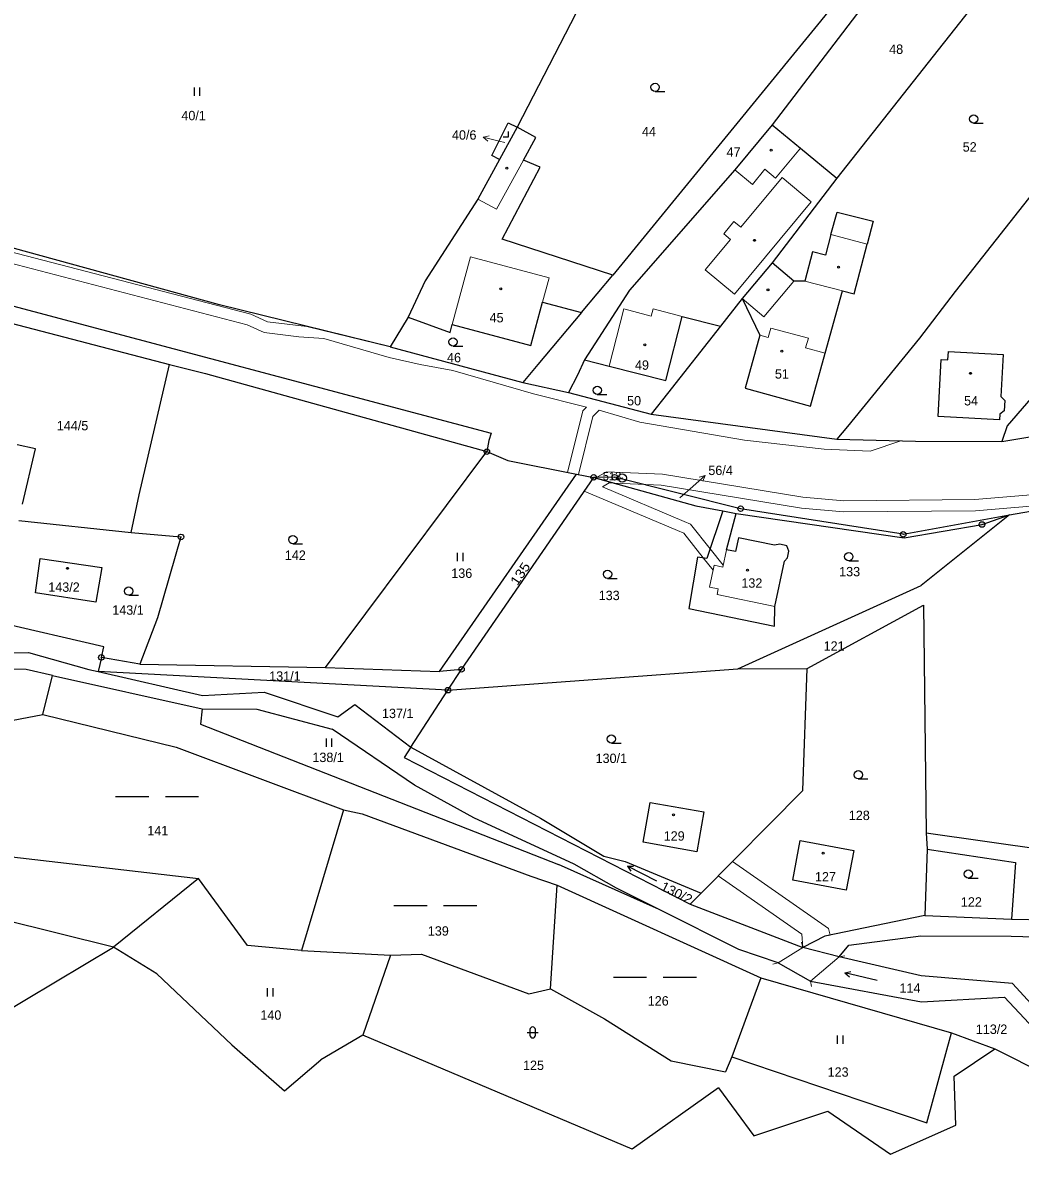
# Model space of a CAD drawing. Extents: x -727701 to -724405, y -960481 to -957284.
# Drawn here: x -726527.9 to -726347.6, y -958284.2 to -958076.9 of the extents above; entities that cross this region are included whole.
import ezdxf
from ezdxf.enums import TextEntityAlignment as Align

# ---------------------------------------------------------------- set-up
doc = ezdxf.new("R2010")
doc.units = 0
doc.header["$LTSCALE"] = 0.68
for name, color, linetype, lineweight in [('1', 7, 'Continuous', 25), ('13', 7, 'Continuous', 13), ('3', 7, 'Continuous', 25), ('4', 7, 'Continuous', 13), ('5', 7, 'Continuous', 25), ('7', 7, 'Continuous', 13), ('8', 7, 'Continuous', 25)]:
    doc.layers.add(name, color=color, linetype=linetype, lineweight=lineweight)
doc.layers.add('2', color=7, linetype='Continuous')

msp = doc.modelspace()

# ---------------------------------------------------------------- linework, layer by layer
at = {"layer": '1'}
for p, q in [((-726341.41, -958055.03), (-726380.73, -958104.97)), ((-726373.89, -958064.49), (-726421.22, -958122.51)), ((-726368.44, -958063.92), (-726392.44, -958095.31)), ((-726427.95, -958075.18), (-726438.54, -958095.75)), ((-726438.54, -958095.75), (-726441.73, -958101.6)), ((-726435.16, -958097.6), (-726438.54, -958095.75)), ((-726392.44, -958095.31), (-726399.17, -958103.47)), ((-726392.44, -958095.31), (-726387.34, -958099.52)), ((-726336.78, -958096.77), (-726359.33, -958125.49)), ((-726437.41, -958101.73), (-726435.16, -958097.6)), ((-726387.34, -958099.52), (-726380.73, -958104.97)), ((-726441.73, -958101.6), (-726445.63, -958108.76)), ((-726441.25, -958116.02), (-726434.4, -958103)), ((-726434.4, -958103), (-726437.41, -958101.73)), ((-726399.17, -958103.47), (-726418.2, -958125.25)), ((-726380.73, -958104.97), (-726392.43, -958120.31)), ((-726445.63, -958108.76), (-726455.15, -958123.51)), ((-726381.83, -958115.18), (-726380.71, -958111.11)), ((-726380.71, -958111.11), (-726374.16, -958112.74)), ((-726374.16, -958112.74), (-726375.25, -958116.9)), ((-726381.83, -958115.18), (-726382.79, -958118.88)), ((-726492.36, -958127.89), (-726536.67, -958115.73)), ((-726421.22, -958122.51), (-726441.25, -958116.02)), ((-726377.6, -958125.9), (-726375.25, -958116.9)), ((-726566.79, -958118.23), (-726443.24, -958151.08)), ((-726385.12, -958118.27), (-726386.5, -958123.57)), ((-726382.79, -958118.88), (-726385.12, -958118.27)), ((-726392.43, -958120.31), (-726397.85, -958126.74)), ((-726388.53, -958123.6), (-726392.43, -958120.31)), ((-726325.56, -958121.52), (-726349.96, -958149.77)), ((-726455.15, -958123.51), (-726458.25, -958130.09)), ((-726426.88, -958129.25), (-726421.22, -958122.51)), ((-726386.5, -958123.57), (-726388.53, -958123.6)), ((-726418.2, -958125.25), (-726426.33, -958137.83)), ((-726382.86, -958136.64), (-726379.74, -958125.34)), ((-726379.74, -958125.34), (-726377.6, -958125.9)), ((-726359.33, -958125.49), (-726365.78, -958133.91)), ((-726461.51, -958135.46), (-726492.36, -958127.89)), ((-726436.03, -958135.24), (-726433.93, -958127.37)), ((-726433.93, -958127.37), (-726426.88, -958129.25)), ((-726397.85, -958126.74), (-726401.77, -958131.72)), ((-726397.85, -958126.74), (-726394.67, -958133.38)), ((-726458.25, -958130.09), (-726461.51, -958135.46)), ((-726458.25, -958130.09), (-726450.64, -958132.86)), ((-726426.88, -958129.25), (-726434.77, -958138.64)), ((-726411.65, -958141.55), (-726408.71, -958129.96)), ((-726408.71, -958129.96), (-726401.77, -958131.72)), ((-726531.37, -958130.82), (-726501.37, -958138.64)), ((-726450.64, -958132.86), (-726450.26, -958131.44)), ((-726450.26, -958131.44), (-726436.03, -958135.24)), ((-726401.77, -958131.72), (-726411.37, -958143.91)), ((-726394.67, -958133.38), (-726397.32, -958142.97)), ((-726365.78, -958133.91), (-726378.81, -958149.88)), ((-726461.51, -958135.46), (-726437.48, -958141.93)), ((-726360.67, -958137.83), (-726360.58, -958136.33)), ((-726360.58, -958136.33), (-726350.67, -958136.87)), ((-726426.33, -958137.83), (-726427.64, -958140.61)), ((-726426.33, -958137.83), (-726421.9, -958138.95)), ((-726385.52, -958146.23), (-726382.86, -958136.64)), ((-726362.43, -958148.09), (-726361.87, -958137.77)), ((-726361.87, -958137.77), (-726360.67, -958137.83)), ((-726350.67, -958136.87), (-726351.08, -958144.46)), ((-726506.88, -958162.26), (-726501.37, -958138.64)), ((-726501.37, -958138.64), (-726494.88, -958140.3)), ((-726494.88, -958140.3), (-726444, -958154.43)), ((-726434.77, -958138.64), (-726437.48, -958141.93)), ((-726421.9, -958138.95), (-726411.65, -958141.55)), ((-726437.48, -958141.93), (-726429.23, -958143.74)), ((-726427.64, -958140.61), (-726429.23, -958143.74)), ((-726429.23, -958143.74), (-726414.32, -958147.68)), ((-726411.37, -958143.91), (-726414.32, -958147.68)), ((-726397.32, -958142.97), (-726385.52, -958146.23)), ((-726351.08, -958144.46), (-726350.39, -958145.17)), ((-726350.39, -958145.17), (-726350.49, -958147.06)), ((-726414.32, -958147.68), (-726380.77, -958152.2)), ((-726351.31, -958148.69), (-726362.43, -958148.09)), ((-726351.26, -958147.67), (-726351.31, -958148.69)), ((-726350.49, -958147.06), (-726351.26, -958147.67)), ((-726350.91, -958152.58), (-726326.11, -958148.57)), ((-726378.81, -958149.88), (-726380.77, -958152.2)), ((-726349.96, -958149.77), (-726350.91, -958152.58)), ((-726443.62, -958152.4), (-726444, -958154.43)), ((-726443.24, -958151.08), (-726443.62, -958152.4)), ((-726380.77, -958152.2), (-726366.52, -958152.55)), ((-726366.52, -958152.55), (-726350.91, -958152.58)), ((-726525.61, -958153.92), (-726528.91, -958153.17)), ((-726527.94, -958163.96), (-726525.61, -958153.92)), ((-726473.15, -958193.5), (-726444, -958154.43)), ((-726444, -958154.43), (-726440.23, -958156.02)), ((-726440.23, -958156.02), (-726427.81, -958158.53)), ((-726452.58, -958194.22), (-726427.81, -958158.53)), ((-726448.58, -958193.81), (-726424.69, -958159.08)), ((-726427.81, -958158.53), (-726424.69, -958159.08)), ((-726424.69, -958159.08), (-726406.26, -958164.21)), ((-726508.31, -958169.06), (-726506.88, -958162.26)), ((-726349.55, -958165.85), (-726324.7, -958161.6)), ((-726406.26, -958164.21), (-726401.37, -958165.16)), ((-726401.37, -958165.16), (-726404.22, -958173.73)), ((-726401.37, -958165.16), (-726398.97, -958165.63)), ((-726368.75, -958169.38), (-726398.13, -958164.75)), ((-726528.64, -958166.9), (-726508.31, -958169.06)), ((-726400.7, -958172.18), (-726398.97, -958165.63)), ((-726398.97, -958165.63), (-726368.6, -958170)), ((-726368.75, -958169.38), (-726349.55, -958165.85)), ((-726349.55, -958165.85), (-726365.47, -958178.66)), ((-726354.5, -958167.6), (-726349.55, -958165.85)), ((-726508.31, -958169.06), (-726499.31, -958169.86)), ((-726368.6, -958170), (-726354.5, -958167.6)), ((-726499.31, -958169.86), (-726503.56, -958184.46)), ((-726398.51, -958169.99), (-726399.04, -958172.52)), ((-726392.01, -958171.35), (-726398.51, -958169.99)), ((-726391.06, -958171.19), (-726392.01, -958171.35)), ((-726389.79, -958171.46), (-726391.06, -958171.19)), ((-726389.44, -958172.44), (-726389.79, -958171.46)), ((-726405.9, -958173.49), (-726407.47, -958182.78)), ((-726404.22, -958173.73), (-726405.9, -958173.49)), ((-726399.04, -958172.52), (-726400.7, -958172.18)), ((-726390.22, -958174.22), (-726389.68, -958173.62)), ((-726389.68, -958173.62), (-726389.44, -958172.44)), ((-726525.61, -958179.99), (-726524.74, -958173.78)), ((-726524.74, -958173.78), (-726513.58, -958175.4)), ((-726513.58, -958175.4), (-726514.69, -958181.65)), ((-726391.94, -958182.43), (-726390.22, -958174.22)), ((-726398.64, -958193.73), (-726365.47, -958178.66)), ((-726514.69, -958181.65), (-726525.61, -958179.99)), ((-726407.47, -958182.78), (-726392.01, -958186)), ((-726392.01, -958186), (-726391.94, -958182.43)), ((-726386.1, -958193.63), (-726365.05, -958182.22)), ((-726365.05, -958182.22), (-726364.62, -958223.38)), ((-726513.25, -958189.75), (-726533.62, -958184.99)), ((-726503.56, -958184.46), (-726506.71, -958192.87)), ((-726513.69, -958191.65), (-726513.25, -958189.75)), ((-726547.93, -958190.97), (-726526.87, -958190.73)), ((-726526.87, -958190.73), (-726515.98, -958193.81)), ((-726513.69, -958191.65), (-726514.28, -958194.2)), ((-726506.71, -958192.87), (-726513.69, -958191.65)), ((-726527.26, -958193.85), (-726547.92, -958193.53)), ((-726515.98, -958193.81), (-726514.28, -958194.2)), ((-726451.04, -958197.58), (-726514.28, -958194.2)), ((-726514.28, -958194.2), (-726495.39, -958198.54)), ((-726506.71, -958192.87), (-726473.15, -958193.5)), ((-726473.15, -958193.5), (-726452.58, -958194.22)), ((-726448.58, -958193.81), (-726452.58, -958194.22)), ((-726451.04, -958197.58), (-726398.64, -958193.73)), ((-726451.04, -958197.58), (-726448.58, -958193.81)), ((-726398.64, -958193.73), (-726386.1, -958193.63)), ((-726386.86, -958215.72), (-726386.1, -958193.63)), ((-726522.53, -958194.9), (-726495.46, -958200.94)), ((-726495.39, -958198.54), (-726484.26, -958197.94)), ((-726484.26, -958197.94), (-726470.96, -958202.37)), ((-726457.73, -958207.91), (-726451.04, -958197.58)), ((-726535.63, -958204.12), (-726524.27, -958202)), ((-726524.27, -958202), (-726500.16, -958207.91)), ((-726495.46, -958200.94), (-726495.77, -958203.74)), ((-726495.46, -958200.94), (-726485.61, -958200.98)), ((-726485.61, -958200.98), (-726471.99, -958204.61)), ((-726495.77, -958203.74), (-726431.08, -958229.1)), ((-726457.1, -958214.78), (-726471.99, -958204.61)), ((-726500.16, -958207.91), (-726469.94, -958219.24)), ((-726457.73, -958207.91), (-726458.93, -958209.76)), ((-726457.73, -958207.91), (-726434.3, -958220.71)), ((-726458.93, -958209.76), (-726407.28, -958236.29)), ((-726446.37, -958220.65), (-726457.1, -958214.78)), ((-726405.26, -958234.26), (-726386.86, -958215.72)), ((-726469.94, -958219.24), (-726477.53, -958244.63)), ((-726469.94, -958219.24), (-726466.57, -958219.95)), ((-726415.74, -958225.05), (-726414.46, -958217.87)), ((-726466.57, -958219.95), (-726436.03, -958231.2)), ((-726428.2, -958229.07), (-726446.37, -958220.65)), ((-726434.3, -958220.71), (-726422.89, -958227.62)), ((-726364.62, -958223.38), (-726364.41, -958226.35)), ((-726364.62, -958223.38), (-726335.35, -958227.55)), ((-726406.05, -958226.79), (-726415.74, -958225.05)), ((-726388.71, -958231.93), (-726387.35, -958224.74)), ((-726387.35, -958224.74), (-726377.67, -958226.56)), ((-726537.55, -958226.85), (-726496.15, -958231.66)), ((-726422.89, -958227.62), (-726418.99, -958228.58)), ((-726377.67, -958226.56), (-726379.03, -958233.75)), ((-726364.41, -958226.35), (-726364.84, -958238.31)), ((-726364.41, -958226.35), (-726348.47, -958228.72)), ((-726412.85, -958237.27), (-726431.08, -958229.1)), ((-726420.55, -958233.4), (-726428.2, -958229.07)), ((-726348.47, -958228.72), (-726349.16, -958238.96)), ((-726496.15, -958231.66), (-726511.47, -958244.03)), ((-726487.3, -958243.78), (-726496.15, -958231.66)), ((-726436.03, -958231.2), (-726431.31, -958232.86)), ((-726432.52, -958251.59), (-726431.31, -958232.86)), ((-726431.31, -958232.86), (-726394.5, -958249.61)), ((-726412.85, -958237.27), (-726420.55, -958233.4)), ((-726379.03, -958233.75), (-726388.71, -958231.93)), ((-726398.45, -958244.5), (-726412.85, -958237.27)), ((-726407.28, -958236.29), (-726386.9, -958244.1)), ((-726511.47, -958244.03), (-726531.6, -958239.03)), ((-726364.84, -958238.31), (-726382.94, -958242.09)), ((-726364.84, -958238.31), (-726349.16, -958238.96)), ((-726349.16, -958238.96), (-726301.76, -958240.07)), ((-726382.94, -958242.09), (-726386.9, -958244.1)), ((-726378.6, -958243.7), (-726365.55, -958241.98)), ((-726365.55, -958241.98), (-726349.22, -958242.08)), ((-726349.22, -958242.08), (-726301.43, -958243.43)), ((-726578.57, -958284.19), (-726511.47, -958244.03)), ((-726503.69, -958248.88), (-726511.47, -958244.03)), ((-726477.53, -958244.63), (-726487.3, -958243.78)), ((-726380.3, -958245.8), (-726386.9, -958244.1)), ((-726380.3, -958245.8), (-726378.6, -958243.7)), ((-726477.53, -958244.63), (-726461.44, -958245.53)), ((-726461.44, -958245.53), (-726466.43, -958259.95)), ((-726461.44, -958245.53), (-726455.84, -958245.35)), ((-726455.84, -958245.35), (-726436.44, -958252.48)), ((-726391.35, -958246.9), (-726398.45, -958244.5)), ((-726365.48, -958249.26), (-726380.3, -958245.8)), ((-726391.35, -958246.9), (-726385.5, -958250.2)), ((-726490.12, -958261.71), (-726503.69, -958248.88)), ((-726394.5, -958249.61), (-726399.74, -958263.87)), ((-726394.5, -958249.61), (-726360, -958259.56)), ((-726385.5, -958250.2), (-726365.41, -958253.96)), ((-726348.99, -958250.64), (-726365.48, -958249.26)), ((-726436.44, -958252.48), (-726432.52, -958251.59)), ((-726432.52, -958251.59), (-726422.73, -958256.99)), ((-726341.86, -958258.44), (-726348.99, -958250.64)), ((-726365.41, -958253.96), (-726350.44, -958253.08)), ((-726350.44, -958253.08), (-726343.31, -958260.71)), ((-726422.73, -958256.99), (-726410.7, -958264.63)), ((-726466.43, -958259.95), (-726474.02, -958264.45)), ((-726417.77, -958280.57), (-726466.43, -958259.95)), ((-726364.47, -958275.82), (-726360, -958259.56)), ((-726360, -958259.56), (-726352.17, -958262.44)), ((-726490.12, -958261.71), (-726480.58, -958270.04)), ((-726359.55, -958267.39), (-726352.17, -958262.44)), ((-726352.17, -958262.44), (-726337.5, -958269.82)), ((-726480.58, -958270.04), (-726474.02, -958264.45)), ((-726410.7, -958264.63), (-726400.85, -958266.59)), ((-726399.74, -958263.87), (-726400.85, -958266.59)), ((-726399.74, -958263.87), (-726364.47, -958275.82)), ((-726359.21, -958276.27), (-726359.55, -958267.39)), ((-726402.12, -958269.47), (-726417.77, -958280.57)), ((-726402.12, -958269.47), (-726395.76, -958278.17)), ((-726395.76, -958278.17), (-726382.38, -958273.74)), ((-726382.38, -958273.74), (-726371.05, -958281.51)), ((-726371.05, -958281.51), (-726359.21, -958276.27))]:
    msp.add_line(p, q, dxfattribs=at)
for points in [[(-726441.73, -958101.6), (-726443.08, -958100.88), (-726440.15, -958094.95), (-726438.54, -958095.75)], [(-726398.13, -958164.75), (-726420.91, -958159.06), (-726424.69, -958159.08)], [(-726524.27, -958202), (-726522.53, -958194.9), (-726527.26, -958193.85)], [(-726470.96, -958202.37), (-726467.89, -958200.16), (-726457.73, -958207.91)], [(-726414.46, -958217.87), (-726404.76, -958219.6), (-726406.05, -958226.79)], [(-726418.99, -958228.58), (-726405.26, -958234.26), (-726407.28, -958236.29)]]:
    msp.add_lwpolyline(points, dxfattribs=at)
at = {"layer": '13'}
msp.add_lwpolyline([(-726548.35, -958115.6), (-726487.36, -958131.48), (-726484.24, -958132.88), (-726478.01, -958133.68), (-726473.49, -958133.97), (-726461.68, -958137.4), (-726456.07, -958138.69), (-726450.13, -958139.78), (-726435.6, -958143.97), (-726425.99, -958146.37), (-726426.66, -958147.06), (-726429.43, -958158.2), (-726427.46, -958158.59), (-726424.85, -958148.07), (-726423.73, -958146.92), (-726416.37, -958149.08), (-726397.46, -958152.36), (-726383.05, -958154.01), (-726374.7, -958154.35), (-726369.16, -958152.49), (-726380.77, -958152.2), (-726414.32, -958147.68), (-726429.23, -958143.74), (-726437.48, -958141.93), (-726461.51, -958135.46), (-726476.56, -958131.77), (-726483.69, -958130.93), (-726486.7, -958129.58), (-726547.8, -958113.68)], dxfattribs=at)
for points in [[(-726330.19, -958149.23), (-726328.99, -958152.11), (-726327.63, -958160.74), (-726355.78, -958163.11), (-726379.48, -958163.31), (-726386.9, -958162.69), (-726412.26, -958158.49), (-726422.38, -958158.07), (-726424.3, -958159.19), (-726420.88, -958160.14), (-726412.47, -958160.48), (-726387.15, -958164.67), (-726379.56, -958165.31), (-726355.68, -958165.11), (-726335.05, -958163.37), (-726324.7, -958161.6), (-726308.26, -958156.96), (-726325.65, -958160.46), (-726327.06, -958151.56), (-726328.16, -958148.9)], [(-726424.69, -958159.08), (-726426.42, -958161.6), (-726409.54, -958168.72), (-726408.43, -958169.19), (-726404.9, -958173.63), (-726403.11, -958175.88), (-726402.92, -958174.98), (-726401.36, -958175.3), (-726401.29, -958174.96), (-726403.65, -958172), (-726407.19, -958167.55), (-726408.33, -958167.07), (-726423.12, -958160.82), (-726421.88, -958160.1), (-726420.88, -958160.14), (-726424.3, -958159.19)], [(-726386.9, -958244.1), (-726382.94, -958242.09), (-726381.95, -958241.88), (-726382.27, -958240.68), (-726399.63, -958228.59), (-726402.19, -958231.16), (-726387.07, -958241.68)]]:
    msp.add_lwpolyline(points, close=True, dxfattribs=at)
at = {"layer": '3'}
for p, q in [((-726496.871, -958090.09), (-726496.871, -958088.59)), ((-726495.87, -958090.09), (-726495.87, -958088.59)), ((-726413.603, -958089.28), (-726411.853, -958089.28)), ((-726356.013, -958095.01), (-726354.263, -958095.01)), ((-726450.123, -958135.34), (-726448.373, -958135.34)), ((-726424.043, -958144.09), (-726422.293, -958144.09)), ((-726479.063, -958171.09), (-726477.313, -958171.09)), ((-726449.311, -958174.23), (-726449.311, -958172.73)), ((-726448.31, -958174.23), (-726448.31, -958172.73)), ((-726378.583, -958174.17), (-726376.833, -958174.17)), ((-726422.183, -958177.36), (-726420.433, -958177.36)), ((-726508.753, -958180.4), (-726507.003, -958180.4)), ((-726473.021, -958207.83), (-726473.021, -958206.33)), ((-726472.02, -958207.83), (-726472.02, -958206.33)), ((-726421.503, -958207.16), (-726419.753, -958207.16)), ((-726376.863, -958213.63), (-726375.113, -958213.63)), ((-726511.119, -958216.82), (-726505.119, -958216.82)), ((-726502.119, -958216.82), (-726496.119, -958216.82)), ((-726418.604, -958229.413), (-726417.506, -958229.409)), ((-726356.973, -958231.58), (-726355.223, -958231.58)), ((-726460.819, -958236.52), (-726454.819, -958236.52)), ((-726451.819, -958236.52), (-726445.819, -958236.52)), ((-726421.119, -958249.49), (-726415.119, -958249.49)), ((-726412.119, -958249.49), (-726406.119, -958249.49)), ((-726379.288, -958248.713), (-726378.223, -958248.444)), ((-726483.651, -958252.99), (-726483.651, -958251.49)), ((-726482.65, -958252.99), (-726482.65, -958251.49)), ((-726436.721, -958259.471), (-726434.719, -958259.471)), ((-726436.221, -958258.971), (-726436.221, -958259.972)), ((-726435.219, -958259.972), (-726435.219, -958258.971)), ((-726380.601, -958261.54), (-726380.601, -958260.04)), ((-726379.6, -958261.54), (-726379.6, -958260.04))]:
    msp.add_line(p, q, dxfattribs=at)
for points in [[(-726441.081, -958097.52), (-726440.08, -958097.52), (-726440.08, -958096.52)], [(-726413.258, -958232.137), (-726418.604, -958229.413), (-726417.961, -958230.303)], [(-726373.442, -958250.063), (-726379.288, -958248.713), (-726378.449, -958249.421)]]:
    msp.add_lwpolyline(points, dxfattribs=at)
for centre in [(-726413.6029, -958088.5298), (-726356.0129, -958094.2598), (-726450.1229, -958134.5898), (-726424.0429, -958143.3398), (-726479.0629, -958170.3398), (-726378.5829, -958173.4198), (-726422.1829, -958176.6098), (-726508.7529, -958179.6498), (-726421.5029, -958206.4098), (-726376.8629, -958212.8798), (-726356.9729, -958230.8298)]:
    msp.add_circle(centre, 0.75, dxfattribs=at)
for centre, start, end in [((-726435.72, -958258.9709), 0, 180), ((-726435.72, -958259.9709), 180, 359.98789)]:
    msp.add_arc(centre, 0.5, start, end, dxfattribs=at)
at = {"layer": '4'}
for p, q in [((-726387.34, -958099.52), (-726391.82, -958104.95)), ((-726437.41, -958101.73), (-726442.25, -958110.6)), ((-726396, -958106.09), (-726399.17, -958103.47)), ((-726398.12, -958113.85), (-726390.64, -958104.85)), ((-726393.75, -958103.36), (-726396, -958106.09)), ((-726391.82, -958104.95), (-726393.75, -958103.36)), ((-726390.64, -958104.85), (-726385.37, -958109.22)), ((-726442.25, -958110.6), (-726445.63, -958108.76)), ((-726385.37, -958109.22), (-726399.25, -958125.94)), ((-726401.19, -958115.04), (-726399.35, -958112.83)), ((-726399.35, -958112.83), (-726398.12, -958113.85)), ((-726399.96, -958116.07), (-726401.19, -958115.04)), ((-726381.83, -958115.18), (-726375.25, -958116.9)), ((-726404.52, -958121.57), (-726399.96, -958116.07)), ((-726450.26, -958131.44), (-726446.99, -958119.17)), ((-726446.99, -958119.17), (-726432.76, -958122.97)), ((-726399.25, -958125.94), (-726404.52, -958121.57)), ((-726432.76, -958122.97), (-726433.93, -958127.37)), ((-726388.53, -958123.6), (-726393.95, -958130.02)), ((-726379.74, -958125.34), (-726386.5, -958123.57)), ((-726393.95, -958130.02), (-726397.85, -958126.74)), ((-726421.9, -958138.95), (-726419.27, -958128.58)), ((-726419.27, -958128.58), (-726414.29, -958129.95)), ((-726414.29, -958129.95), (-726413.95, -958128.63)), ((-726413.95, -958128.63), (-726408.71, -958129.96)), ((-726393.13, -958133.8), (-726392.65, -958132.07)), ((-726392.65, -958132.07), (-726385.89, -958133.89)), ((-726394.67, -958133.38), (-726393.13, -958133.8)), ((-726385.89, -958133.89), (-726386.38, -958135.67)), ((-726386.38, -958135.67), (-726382.86, -958136.64)), ((-726401.36, -958175.3), (-726400.7, -958172.18)), ((-726403.75, -958178.94), (-726402.92, -958174.98)), ((-726402.92, -958174.98), (-726401.36, -958175.3)), ((-726402.19, -958179.26), (-726403.75, -958178.94)), ((-726402.39, -958180.24), (-726402.19, -958179.26)), ((-726391.94, -958182.43), (-726402.39, -958180.24)), ((-726386.9, -958244.1), (-726391.35, -958246.9)), ((-726387.158, -958243.134), (-726386.9, -958244.099)), ((-726380.3, -958245.8), (-726385.5, -958250.2)), ((-726379.312, -958245.644), (-726380.299, -958245.8)), ((-726392.321, -958247.141), (-726391.351, -958246.9)), ((-726385.327, -958251.185), (-726385.5, -958250.201))]:
    msp.add_line(p, q, dxfattribs=at)
at = {"layer": '5'}
for centre in [(-726392.6068, -958099.8992), (-726440.3968, -958103.1692), (-726395.6368, -958116.2092), (-726380.4168, -958121.0592), (-726441.5068, -958124.9992), (-726393.1868, -958125.1592), (-726415.4668, -958135.0992), (-726390.6668, -958136.2692), (-726356.5568, -958140.2692), (-726519.8168, -958175.5392), (-726396.9068, -958175.8492), (-726410.2568, -958220.1192), (-726383.1968, -958227.0392)]:
    msp.add_circle(centre, 0.175, dxfattribs=at)
at = {"layer": '7'}
for p, q in [((-726444.672, -958097.534), (-726443.821, -958098.262)), ((-726404.515, -958158.751), (-726405.599, -958159.03))]:
    msp.add_line(p, q, dxfattribs=at)
for points in [[(-726440.74, -958098.51), (-726441.76, -958098.26), (-726444.672, -958097.534), (-726443.579, -958097.29)], [(-726409.12, -958162.78), (-726406.78, -958160.72), (-726404.515, -958158.751), (-726404.942, -958159.786)]]:
    msp.add_lwpolyline(points, dxfattribs=at)
at = {"layer": '8'}
for centre, radius in [((-726444, -958154.4299), 0.5), ((-726444, -958154.4299), 0.0303), ((-726424.69, -958159.0799), 0.5), ((-726424.69, -958159.0799), 0.0303), ((-726420.91, -958159.0599), 0.5), ((-726420.91, -958159.0599), 0.0303), ((-726419.54, -958159.1898), 0.75), ((-726419.54, -958159.1898), 0.03), ((-726398.13, -958164.7499), 0.5), ((-726398.13, -958164.7499), 0.0303), ((-726354.5, -958167.5999), 0.5), ((-726499.31, -958169.8599), 0.5), ((-726368.75, -958169.3799), 0.5), ((-726368.75, -958169.3799), 0.0303), ((-726354.5, -958167.5999), 0.0303), ((-726499.31, -958169.8599), 0.0303), ((-726513.69, -958191.6499), 0.5), ((-726513.69, -958191.6499), 0.0303), ((-726448.58, -958193.8099), 0.5), ((-726448.58, -958193.8099), 0.0303), ((-726451.04, -958197.5799), 0.5), ((-726451.04, -958197.5799), 0.0303)]:
    msp.add_circle(centre, radius, dxfattribs=at)

# ---------------------------------------------------------------- texts
at = {"layer": '2'}
for s, p in [('48', (-726371.28, -958082.495)), ('40/1', (-726499.23, -958094.495)), ('44', (-726415.98, -958097.395)), ('52', (-726357.99, -958100.165)), ('47', (-726400.68, -958101.105)), ('45', (-726443.52, -958131.055)), ('46', (-726451.21, -958138.265)), ('49', (-726417.23, -958139.625)), ('51', (-726391.94, -958141.215)), ('50', (-726418.66, -958146.065)), ('54', (-726357.74, -958146.075)), ('56/4', (-726403.97, -958158.665)), ('142', (-726480.53, -958174.005)), ('136', (-726450.44, -958177.265)), ('132', (-726398, -958179.045)), ('143/2', (-726523.29, -958179.785)), ('133', (-726423.79, -958181.285)), ('121', (-726383.13, -958190.435)), ('128', (-726378.58, -958221.065)), ('141', (-726505.39, -958223.825)), ('129', (-726412.04, -958224.795)), ('127', (-726384.7, -958232.175)), ('122', (-726358.32, -958236.725)), ('139', (-726454.68, -958241.975)), ('114', (-726369.41, -958252.305)), ('126', (-726414.93, -958254.615)), ('140', (-726484.95, -958257.185)), ('125', (-726437.47, -958266.275)), ('123', (-726382.41, -958267.485))]:
    msp.add_text(s, height=1.7, dxfattribs=at).set_placement(p)
for s, p in [('40/6', (-726448.099, -958098.005)), ('144/5', (-726518.9, -958150.575)), ('133', (-726378.429, -958176.985)), ('143/1', (-726508.88, -958183.925)), ('131/1', (-726480.51, -958195.875)), ('137/1', (-726460.12, -958202.625)), ('138/1', (-726472.7, -958210.575)), ('130/1', (-726421.51, -958210.745)), ('113/2', (-726352.77, -958259.745))]:
    msp.add_text(s, height=1.7, dxfattribs=at).set_placement(p, align=Align.CENTER)
at = {"layer": '2', "width": 1.15}
msp.add_text('135', height=1.7, rotation=56, dxfattribs=at).set_placement((-726438.497, -958178.797))
at = {"layer": '2', "width": 1.05}
msp.add_text('130/2', height=1.7, rotation=333, dxfattribs=at).set_placement((-726410.0754, -958234.9787), align=Align.CENTER)
at = {"layer": '8'}
msp.add_text('513', height=1.5, dxfattribs=at).set_placement((-726423.05, -958159.615))

doc.saveas('drawing.dxf')
